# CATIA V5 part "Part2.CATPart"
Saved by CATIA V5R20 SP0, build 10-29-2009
Part number: Part2
Bounding box of the stored display mesh (mm): x -23 to 23, y -53.627 to 53.627, z 8 to 48
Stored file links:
  C:\Users\Ehsan Fathi\Desktop\New folder\Assembly Design No.28\Part2.CATPart
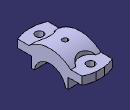
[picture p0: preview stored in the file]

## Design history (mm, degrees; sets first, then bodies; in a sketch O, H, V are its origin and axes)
Body1 (main body)
  DatumCurve1
  Sketch1 on yz-plane, origin (0, 0, 0), H (0, 1, 0), V (0, 0, 1)
    line L1 (23.6643, 8) -> (27.6274, 8)
    line L2 (27.6274, 8) -> (27.6274, 24)
    line L3 (27.6274, 24) -> (53.6274, 24)
    line L4 (53.6274, 24) -> (53.6274, 36)
    line L5 (53.6274, 36) -> (31.749, 36)
    line L6 (-23.6643, 8) -> (-27.6274, 8)
    line L7 (-27.6274, 8) -> (-27.6274, 24)
    line L8 (-27.6274, 24) -> (-53.6274, 24)
    line L9 (-53.6274, 24) -> (-53.6274, 36)
    line L10 (-53.6274, 36) -> (-31.749, 36)
    arc A1 centre (0, 0) radius 48 from (31.749, 36) to (-31.749, 36) ccw
    projected circle E1 centre (0, 4) radius 24 from edge of DatumCurve1
    projected arc E2 centre (0, 4) radius 24 from (23.6643, 8) to (-23.6643, 8) ccw from edge of DatumCurve1
  Pad1: profile Sketch1, direction (1, 0, 0), length 23, mirrored extent
  Sketch2 on face of Pad1 from Sketch1.L5, origin (0, 0, 36), H (1, 0, 0), V (0, 1, 0)
    circle A1 centre (0, 39) radius 6
    circle A2 centre (0, -39) radius 6
    circle A3 centre (0, 39) radius 17
    circle A4 centre (0, -39) radius 17
  Pocket1: profile Sketch2, direction (0, 0, -1), length -26
  Sketch3 on face of Pocket1, origin (0, 0, 36), H (1, 0, 0), V (0, 1, 0)
    line L1 (24.9916, 47.8688) -> (25.2576, 59.6175)
    line L2 (25.2576, 59.6175) -> (-28.6371, 59.6175)
    line L3 (-28.6371, 59.6175) -> (-29.0993, 45.4888)
    line L4 (-27.7968, -46.2962) -> (-28.2232, -65.0886)
    line L5 (-28.2232, -65.0886) -> (33.4798, -68.1799)
    line L6 (33.4798, -68.1799) -> (32.989, -42.7519)
    arc A1 centre (0, 0) radius 54 from (24.9916, 47.8688) to (-29.0993, 45.4888) ccw
    arc A2 centre (0, 0) radius 54 from (-27.7968, -46.2962) to (32.989, -42.7519) ccw
  Pocket2: profile Sketch3, direction (0, 0, 1), through (limit type 3)
  Sketch4 on face of Pocket1, origin (0, 0, 36), H (1, 0, 0), V (0, 1, 0)
    circle A1 centre (0, 0) radius 3
    circle A2 centre (0, 0) radius 4
  MultiPocket1: profile Sketch4, domains (length 0 / length 19; length 5 / length 17)
  Sketch5 on face of Pocket1, origin (0, 0, 36), H (1, 0, 0), V (0, 1, 0)
    circle A1 centre (0, 39) radius 6
    point P2 (0, 33)
    circle A2 centre (0, -39) radius 6
  Pocket3: profile Sketch5, direction (0, 0, -1), through (limit type 6)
